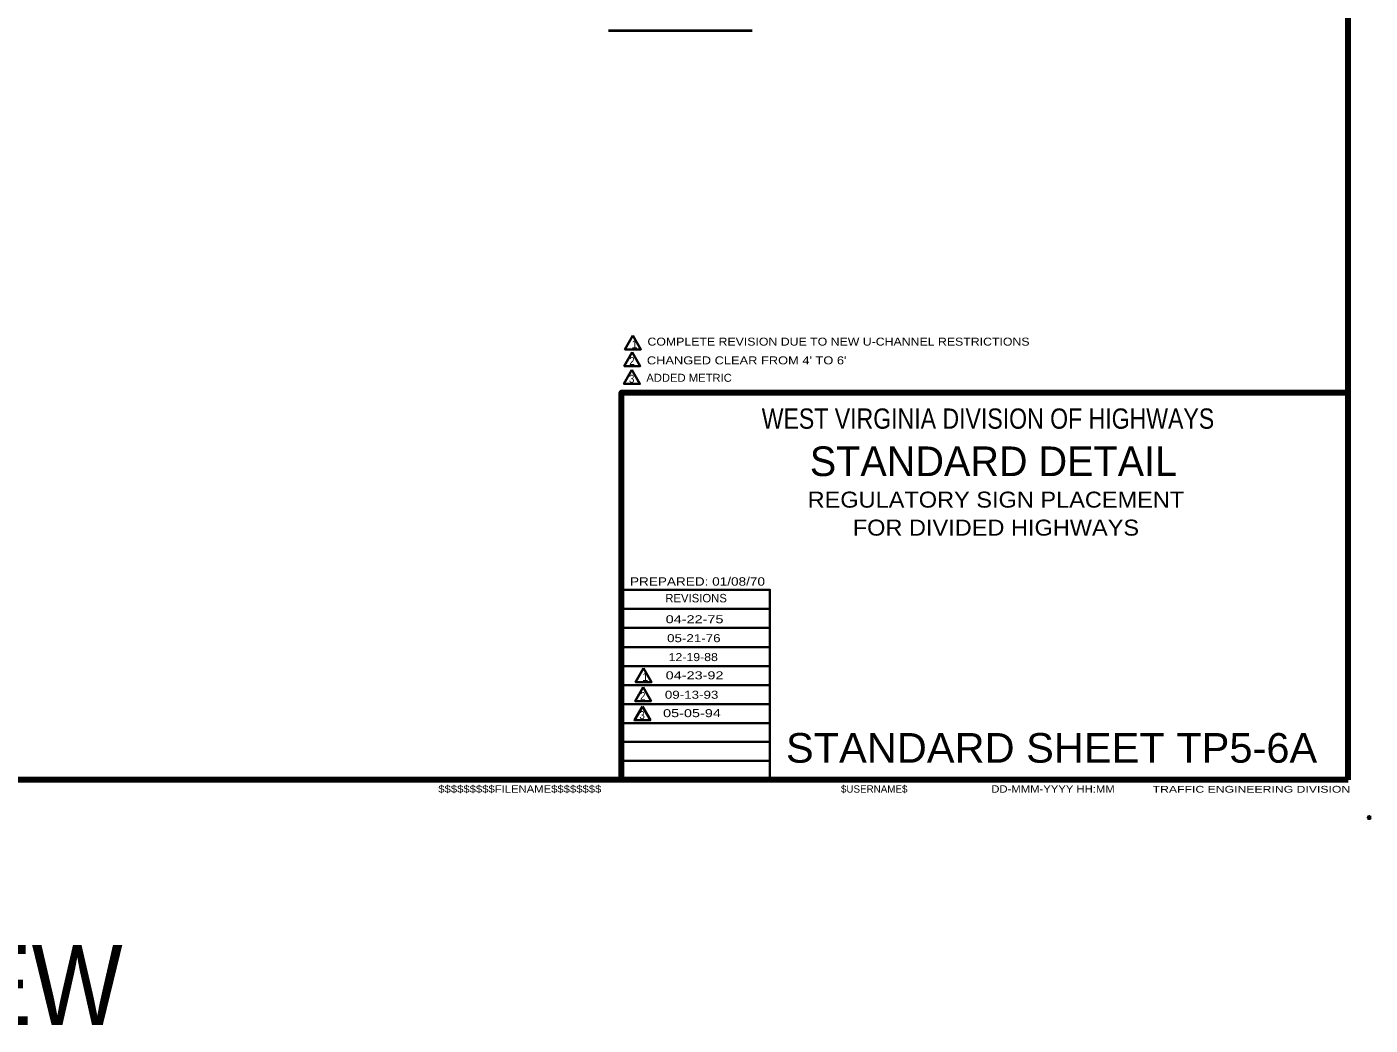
# Model space of a CAD drawing. Extents: x 1081 to 1936, y -630 to -24.
# Drawn here: x 1533.1 to 1936.1, y -629.9 to -330.4 of the extents above; entities that cross this region are included whole.
import ezdxf
from ezdxf.enums import TextEntityAlignment as Align

# ---------------------------------------------------------------- set-up
doc = ezdxf.new("R2010")
doc.units = 0
doc.header["$PDMODE"] = 32
doc.header["$PDSIZE"] = 0.5
doc.layers.add('1', color=7, linetype='Continuous', lineweight=53)
doc.layers.add('61', color=7, linetype='Continuous', lineweight=35)

msp = doc.modelspace()

# ---------------------------------------------------------------- linework, layer by layer
at = {"layer": '1', "lineweight": 158}
for q in [(1929.57, -30.27), (1929.57, -440.07), (1137.97, -556.37)]:
    msp.add_line((1929.57, -556.37), q, dxfattribs=at)
at = {"layer": '1', "lineweight": 13}
msp.add_line((1929.57, -556.37), (1929.57, -30.27), dxfattribs=at)
at = {"layer": '1', "lineweight": 40}
msp.add_line((1707.623, -331.486), (1750.772, -331.486), dxfattribs=at)
at = {"layer": '1', "lineweight": 35}
for p, q in [((1756.07, -504.97), (1711.57, -504.97)), ((1756.07, -510.67), (1711.57, -510.67)), ((1756.07, -516.47), (1711.57, -516.47)), ((1756.07, -522.17), (1711.57, -522.17)), ((1756.07, -527.87), (1711.57, -527.87)), ((1756.07, -533.57), (1711.57, -533.57)), ((1756.07, -539.27), (1711.57, -539.27)), ((1756.07, -544.97), (1711.57, -544.97)), ((1756.07, -550.67), (1711.57, -550.67))]:
    msp.add_line(p, q, dxfattribs=at)
for points in [[(1714.951, -423.012), (1712.551, -427.169), (1717.351, -427.169)], [(1714.779, -428.012), (1712.379, -432.169), (1717.178, -432.169)], [(1714.678, -433.339), (1712.278, -437.496), (1717.078, -437.496)], [(1718.136, -522.83), (1715.736, -526.986), (1720.536, -526.986)], [(1718.005, -528.551), (1715.605, -532.708), (1720.405, -532.708)], [(1717.803, -534.277), (1715.403, -538.433), (1720.203, -538.433)]]:
    msp.add_lwpolyline(points, close=True, dxfattribs=at)
at = {"layer": '1', "lineweight": 158}
msp.add_lwpolyline([(1711.57, -556.37), (1711.57, -440.07), (1929.57, -440.07)], dxfattribs=at)
at = {"layer": '1', "lineweight": 35}
msp.add_lwpolyline([(1756.07, -556.37), (1756.07, -499.27), (1711.57, -499.27)], dxfattribs=at)
at = {"layer": '1'}
msp.add_point((1935.87, -567.67), dxfattribs=at)
at = {"layer": '61', "lineweight": 53}
for q in [(1776.87, -556.37), (1776.87, -556.37), (1776.87, -556.37), (1777.17, -556.37), (1777.17, -556.37)]:
    msp.add_line((1929.57, -556.37), q, dxfattribs=at)

# ---------------------------------------------------------------- texts
at = {"layer": '1'}
for s, height, p in [('1', 2.4, (1715.47, -426.841)), ('STANDARD DETAIL', 8.881, (1823.12, -465.17)), ('1', 2.4, (1718.655, -526.658))]:
    msp.add_text(s, height=height, dxfattribs=at).set_placement(p, align=Align.CENTER)
for s, height, width, p in [('COMPLETE REVISION DUE TO NEW U-CHANNEL RESTRICTIONS', 2.4, 1.15, (1776.632, -426.029)), ('2', 2.4, 0.9, (1714.681, -431.84)), ("CHANGED CLEAR FROM 4' TO 6'", 2.4, 1.2, (1749.084, -431.652)), ('3', 2.4, 0.9, (1714.59, -437.168)), ('ADDED METRIC', 2.4, 1.05, (1731.8, -436.879)), ('WEST VIRGINIA DIVISION OF HIGHWAYS', 6.089, 0.85, (1821.47, -450.97)), ('REGULATORY SIGN PLACEMENT', 4.8, 1.1, (1823.859, -474.641)), ('FOR DIVIDED HIGHWAYS', 4.8, 1.1, (1823.859, -483.041)), ('04-22-75', 2.4, 1.35, (1733.456, -509.333)), ('05-21-76', 2.4, 1.25, (1733.232, -515.012)), ('12-19-88', 2.4, 1.15, (1733.057, -520.691)), ('04-23-92', 2.4, 1.35, (1733.456, -526.17)), ('2', 2.4, 0.9, (1717.908, -532.38)), ('09-13-93', 2.4, 1.25, (1732.568, -531.989)), ('3', 2.4, 0.9, (1717.715, -538.105)), ('05-05-94', 2.4, 1.35, (1732.676, -537.514)), ('NEW', 24, 0.9, (1528.172, -629.936))]:
    msp.add_text(s, height=height, dxfattribs=dict(at, width=width)).set_placement(p, align=Align.CENTER)
for s, height, width, p in [('PREPARED: 01/08/70', 2.537, 1.2, (1714.07, -498.07)), ('STANDARD SHEET TP5-6A', 8.881, 1.05, (1760.87, -551.17)), ('$$$$$$$$$FILENAME$$$$$$$$', 2.2, 1.15, (1656.57, -560.17)), ('DD-MMM-YYYY HH:MM', 2.2, 1.15, (1822.47, -560.17)), ('TRAFFIC ENGINEERING DIVISION', 2.031, 1.35, (1870.87, -560.17))]:
    msp.add_text(s, height=height, dxfattribs=dict(at, width=width)).set_placement(p)
for s, height, p in [('REVISIONS', 2.537, (1724.67, -503.07)), ('$USERNAME$', 2.2, (1777.37, -560.17))]:
    msp.add_text(s, height=height, dxfattribs=at).set_placement(p)

doc.saveas('drawing.dxf')
